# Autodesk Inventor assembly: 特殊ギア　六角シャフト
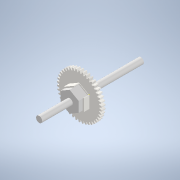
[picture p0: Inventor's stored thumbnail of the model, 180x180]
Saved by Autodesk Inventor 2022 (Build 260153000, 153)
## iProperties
Created: 2024-12
Part Number: 特殊ギア　六角シャフト
Document SubType Name: Assembly
Designer: jsat7
Author: jsat7
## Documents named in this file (4)
- C:\Users\jsat7\OneDrive\デスクトップ\CAD 長田\特殊ギア　六角シャフト.iam
- C:\Users\jsat7\OneDrive\デスクトップ\CAD 長田\六角シャフト.ipt
- C:\Users\jsat7\OneDrive\デスクトップ\CAD 長田\特殊平ギア.ipt
- C:\Users\jsat7\OneDrive\デスクトップ\CAD 長田\固定器具.ipt
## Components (3 placed, 3 different names)
1. 六角シャフト:1 — 回転:1, リジッド:1
2. 平歯車1:1 — 回転:1
3. 固定器具:1 — リジッド:1
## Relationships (2: RevoluteJoint 1, WeldJoint 1)
- 回転:1 [RevoluteJoint]: 六角シャフト:1 ↔ 平歯車1:1
- リジッド:1 [WeldJoint]: 六角シャフト:1 ↔ 固定器具:1
